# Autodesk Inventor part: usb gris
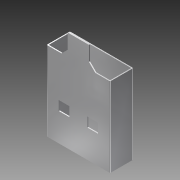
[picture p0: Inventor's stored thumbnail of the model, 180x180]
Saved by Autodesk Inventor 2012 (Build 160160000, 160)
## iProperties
Created: 2013-04
Part Number: usb gris
Material: Default
Document SubType Name: Modeling
Designer: hilarion
Density: 1 g/cm^3
Author: hilarion
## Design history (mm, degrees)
sketch "Esquisse1"
  geometry: L1 (0.2, 0)-(11.8, 0); L2 (12, 0.2)-(12, 4.2); L3 (11.8, 4.4)-(0.2, 4.4); L4 (0, 4.2)-(0, 0.2); L5 (0.3, 4.2)-(11.7, 4.2); L6 (11.8, 4.1)-(11.8, 0.3); L7 (11.7, 0.2)-(0.3, 0.2); L8 (0.2, 0.3)-(0.2, 4.1); A1 r 0.2 centre (0.2, 4.2) between (0.2, 4.4) and (0, 4.2); A2 r 0.1 centre (0.3, 4.1) between (0.3, 4.2) and (0.2, 4.1); A3 r 0.1 centre (0.3, 0.3) between (0.2, 0.3) and (0.3, 0.2); A4 r 0.1 centre (11.7, 0.3) between (11.7, 0.2) and (11.8, 0.3); A5 r 0.1 centre (11.7, 4.1) between (11.8, 4.1) and (11.7, 4.2); A6 r 0.2 centre (0.2, 0.2) between (0, 0.2) and (0.2, 0); A7 r 0.2 centre (11.8, 0.2) between (11.8, 0) and (12, 0.2); A8 r 0.2 centre (11.8, 4.2) between (12, 4.2) and (11.8, 4.4); 4 further points
  constraints: 16 end point, 16 point on circle, 16 tangent, 8 centre point, 8 point on line, 4 equal radius, 4 parallel, 2 perpendicular, 1 horizontal, 3 other
  dimensions: "d0" = 12 distance of point (0, 4.4) point (12, 4.4); "d1" = 4.4 distance of point (12, 4.4) point (12, 0); "d2" = 0.2 distance between parallel lines of L5 L3; "d3" = 0.2 radius of A1; "d4" = 0.1 radius of A2; "d5" = 0.1 radius of A3; "d6" = 0.2 radius of A6
extrude "Extrusion1" new body sketch "Esquisse1" distance "d7" = 15; taper "d8" = 0 deg
sketch "Esquisse2"
  geometry: L1 (11.6, 15)-(0, 15) reference; L2 (0, 0)-(0, 15) reference; L3 (11.6, 0)-(11.6, 15) reference; L4 (3.8, 15)-(7.8, 15); L5 (7.8, 16.2)-(7.8, 19); L6 (7.8, 19)-(3.8, 19); L7 (3.8, 19)-(3.8, 16.2); L8 (2.6, 15)-(0, 15); L9 (9, 15)-(11.6, 15); L10 (7.832, 15)-(8.147, 15); L11 (7.832, 15)-(7.8, 15); L12 (2.6, 15)-(3.8, 16.2); L13 (7.8, 16.2)-(9, 15); L14 (2.6, 15)-(9, 15); 2 further points
  constraints: 22 end point, 9 point on line, 5 collinear, 2 parallel, 1 horizontal, 1 perpendicular
  dimensions: "d9" = 4 distance between parallel lines of L5 L7; "d10" = 4 distance between parallel lines of L1 L6; "d11" = 3.8 distance between parallel lines of L7 L2; "d12" = 3.8 distance between parallel lines of L3 L5 (derived); "d13" = 1.2 distance of L8.start L4.start; "d14" = 1.2 distance of L7.end L4.start (= d13); "d15" = 1.2 distance of L5.start point (7.8, 15) (= d13); "d16" = 1.2 distance of L9.start point (7.8, 15) (= d15)
extrude "Extrusion2" join sketch "Esquisse2" distance "d17" = 0.2; taper "d18" = 0 deg
sketch "Esquisse3"
  geometry: L1 (0, 0)-(0, 15) reference; L2 (11.6, 0)-(0, 0) reference; L3 (11.6, 0)-(11.6, 15) reference; L4 (2.1, 7.1)-(4.1, 7.1); L5 (4.1, 7.1)-(4.1, 5.3); L6 (4.1, 5.3)-(2.1, 5.3); L7 (2.1, 5.3)-(2.1, 7.1); L8 (7.5, 7.1)-(9.5, 7.1); L9 (9.5, 7.1)-(9.5, 5.3); L10 (9.5, 5.3)-(7.5, 5.3); L11 (7.5, 5.3)-(7.5, 7.1); 1 further point
  constraints: 16 end point, 4 parallel, 2 horizontal, 2 perpendicular
  dimensions: "d19" = 5.3 distance between parallel lines of L6 L2; "d20" = 5.3 distance between parallel lines of L2 L10 (= d19); "d21" = 1.8 distance between parallel lines of L4 L6; "d22" = 1.8 distance between parallel lines of L8 L10 (= d21); "d23" = 3.4 distance between parallel lines of L11 L5; "d24" = 2 distance between parallel lines of L5 L7; "d25" = 2 distance between parallel lines of L9 L11; "d26" = 2.09981 distance between parallel lines of L7 L1; "d27" = 2.10019 distance between parallel lines of L3 L9 (derived)
extrude "Extrusion3" cut sketch "Esquisse3" distance "d28" = 0.2; taper "d29" = 0 deg
sketch "Esquisse4"
  geometry: L1 (11.6, 0)-(11.6, -15) reference; L2 (0, 0)-(0, -15) reference; L3 (2.05, -5.3)-(4.05, -5.3); L4 (4.05, -5.3)-(4.05, -6.9); L5 (4.05, -6.9)-(2.05, -6.9); L6 (2.05, -6.9)-(2.05, -5.3); L7 (7.55, -5.3)-(9.55, -5.3); L8 (9.55, -5.3)-(9.55, -6.9); L9 (9.55, -6.9)-(7.55, -6.9); L10 (7.55, -6.9)-(7.55, -5.3); L11 (0, 0)-(11.6, 0) reference; 1 further point
  constraints: 16 end point, 4 parallel, 2 horizontal, 2 perpendicular
  dimensions: "d30" = 2 distance between parallel lines of L4 L6; "d31" = 2 distance between parallel lines of L8 L10 (= d30); "d32" = 3.5 distance between parallel lines of L10 L4; "d33" = 2.05 distance between parallel lines of L6 L2; "d34" = 2.05 distance between parallel lines of L1 L8 (derived); "d37" = 5.3 distance between parallel lines of L11 L3; "d38" = 5.3 distance between parallel lines of L11 L7 (= d37); "d39" = 1.6 distance between parallel lines of L3 L5; "d40" = 1.6 distance between parallel lines of L7 L9 (= d39)
extrude "Extrusion4" cut sketch "Esquisse4" distance "d35" = 0.2; taper "d36" = 0 deg
node "Solide1"
